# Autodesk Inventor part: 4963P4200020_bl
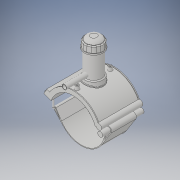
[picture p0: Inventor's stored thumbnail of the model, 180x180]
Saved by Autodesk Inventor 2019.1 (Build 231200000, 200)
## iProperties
Created: 2017-07
Part Number: 4963P4200020_bl
Material: Generic
Document SubType Name: Modeling
Designer: KIM
Density: 1 g/cm^3
Appearance: Default
Author: KIM
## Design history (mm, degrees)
derived "4963P4.ipt"
feature "Solid1::4963P4.ipt" dims "ScaleForDerivedMember" = 10
feature "Solid2::4963P4.ipt" dims "ScaleForDerivedMember" = 10
feature "Solid3::4963P4.ipt" dims "ScaleForDerivedMember" = 10
tag "TaggingFeature1"
body "Solid1"
body "Solid2"
body "Solid3"
other parameters: "B_" = 202 [user parameter], "L_" = 176 [user parameter], "d_t" = 6 [user parameter], "H_2" = 177 [user parameter], "H_" = 125 [user parameter], "d1" = 232 [user parameter], "d148" = 3 [user parameter], "d160" = 3 [user parameter], "d169" = 3 [user parameter], "d192" = 6.4 [user parameter], "d2" = 262.6 [user parameter], "d4" = 176 [user parameter], "d5" = 0 [user parameter], "d6" = 0.1 [user parameter], "d8" = 0 [user parameter], "d19" = 6 [user parameter], "d20" = 6 [user parameter], "d21" = 105.6 [user parameter], "d23" = 0 [user parameter], "d24" = 52.8 [user parameter], "d26" = 0 [user parameter], "d27" = 3 [user parameter], "d28" = 3 [user parameter], "d29" = 3 [user parameter], "d30" = 66.66667 [user parameter], "d31" = 6 [user parameter], "d32" = 0 [user parameter], "d33" = 0 [user parameter], "d34" = 0.6 [user parameter], "d40" = 120.64 [user parameter], "d43" = 0 [user parameter], "d45" = 0 [user parameter], "d47" = 221.6 [user parameter], "d70" = 15 [user parameter], "d72" = 0 [user parameter], "d73" = 6 [user parameter], "d75" = 5 [user parameter], "d76" = 0 [user parameter], "d79" = 15 [user parameter], "d80" = 70.4 [user parameter], "d82" = 5 deg [user parameter], "d84" = 4 [user parameter], "d85" = 14 [user parameter], "d86" = 0 [user parameter], "d87" = 3 [user parameter], "d88" = 0 [user parameter], "d89" = 1 [user parameter], "d90" = 1 [user parameter], "d91" = 140.8 [user parameter], "d92" = 0 [user parameter], "d93" = 0.5 [user parameter], "d94" = 105.26316 [user parameter], "d96" = 236.64 [user parameter], "d97" = 3.52 [user parameter], "d98" = 0 [user parameter], "d102" = 2 [user parameter], "d120" = 140 deg [user parameter], "d121" = 24.228 [user parameter], "d122" = 20 deg [user parameter], "d123" = 464 [user parameter], "d124" = 139.2 [user parameter], "d126" = 0 [user parameter], "d143" = 206 [user parameter], "d145" = 24.61538 [user parameter], "d149" = 3 [user parameter], "d150" = 27.07692 [user parameter], "d153" = 176 [user parameter], "d154" = 0 [user parameter], "d156" = 116 [user parameter], "d157" = 160 deg [user parameter], "d159" = 6.4 [user parameter], "d161" = 3 [user parameter], "d162" = 105.6 [user parameter], "d163" = 0 [user parameter], "d168" = 113.17073 [user parameter], "d170" = 3 [user parameter], "d172" = 0 [user parameter], "d173" = 1 [user parameter], "d176" = 20 deg [user parameter], "d177" = 14 [user parameter], "d178" = 32 [user parameter], "d180" = 0 [user parameter], "d183" = 12.8 [user parameter], "d184" = 11.2 [user parameter], "d185" = 57.2 [user parameter], "d186" = 57.2 [user parameter], "d187" = 116 [user parameter], "d188" = 9.6 [user parameter], "d189" = 14 [user parameter], "d190" = 0 [user parameter], "d191" = 174 [user parameter], "d193" = 6.4 [user parameter], "d194" = 6.16 [user parameter], "d195" = 90 deg [user parameter], "d197" = 0 [user parameter], "d199" = 0 [user parameter], "d200" = 16 [user parameter], "d202" = 0 [user parameter], "d203" = 177 [user parameter], "d204" = 76 [user parameter], "d205" = 56 [user parameter], "d206" = 68 [user parameter], "d207" = 132.75 [user parameter], "d208" = 138.06 [user parameter], "d209" = 164.61 [user parameter], "d210" = 68.8 [user parameter], "d212" = 64 [user parameter], "d213" = 36 [user parameter], "d216" = 0 [user parameter], "d219" = 4 [user parameter], "d224" = 0 [user parameter], "d227" = 16 [user parameter], "d228" = 125 [user parameter], "d230" = 4 [user parameter]
